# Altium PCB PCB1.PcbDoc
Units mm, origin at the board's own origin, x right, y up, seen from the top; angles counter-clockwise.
Board outline 35 x 25 mm, 2 copper layers (Top Layer, Bottom Layer); 9 components, 6 nets, 20 pads, 0 vias.
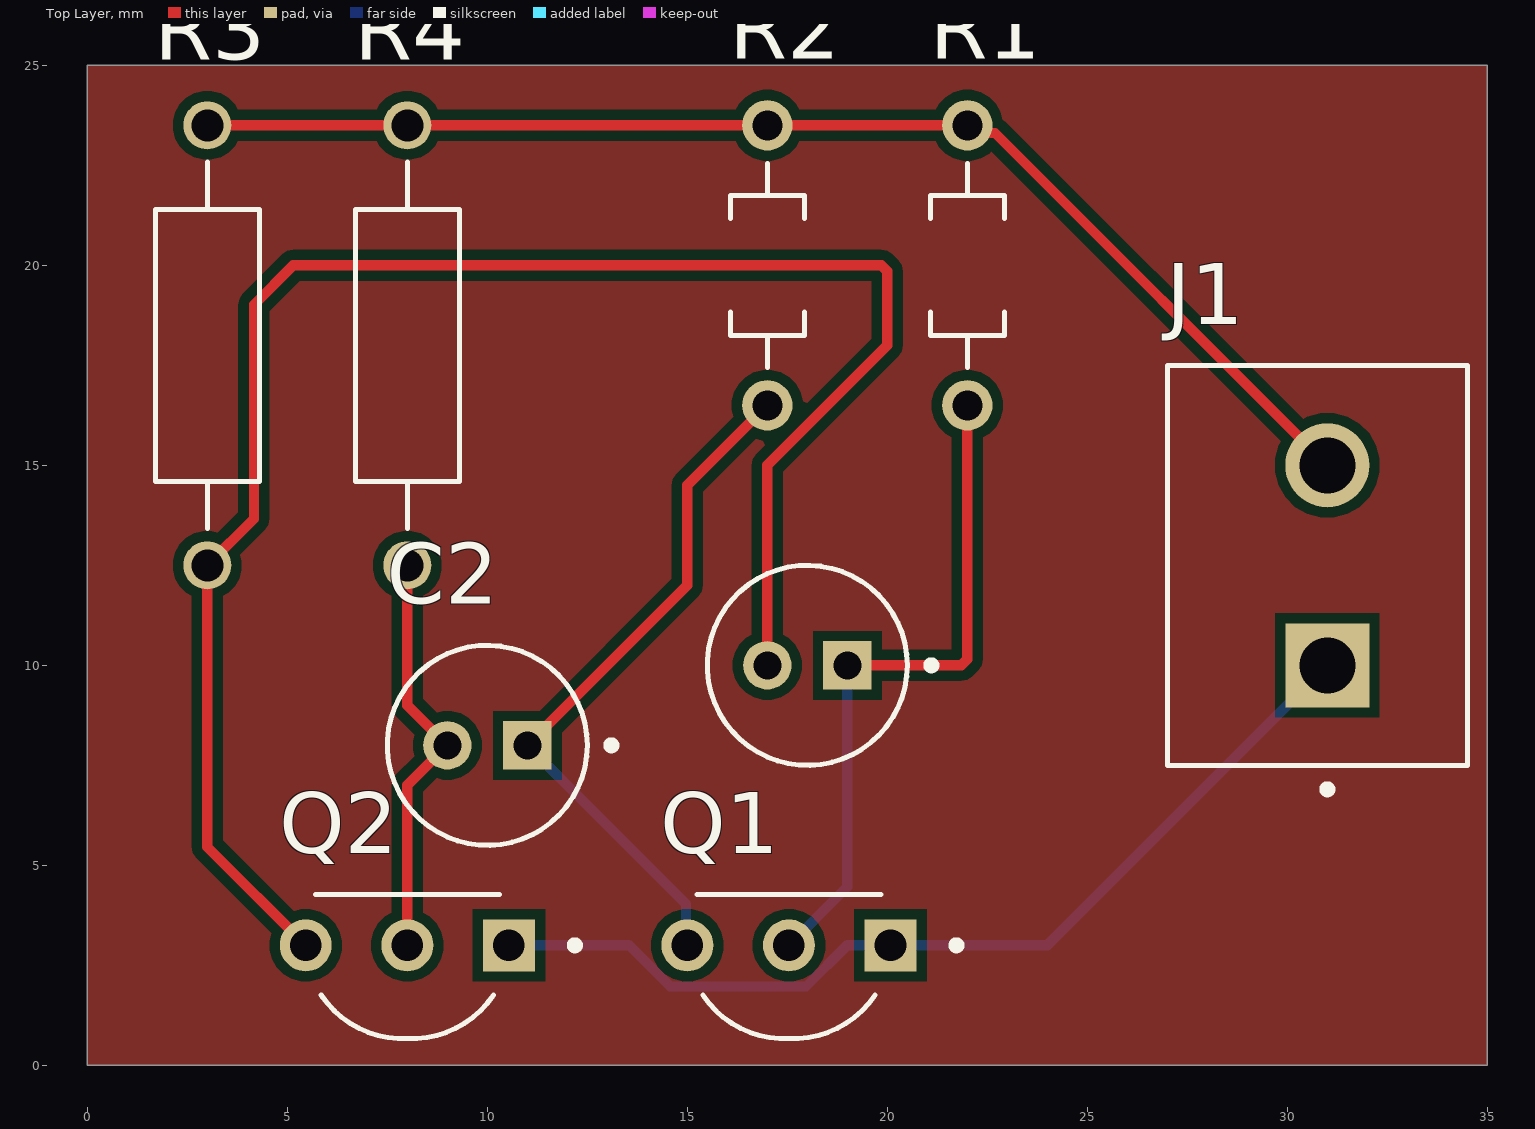
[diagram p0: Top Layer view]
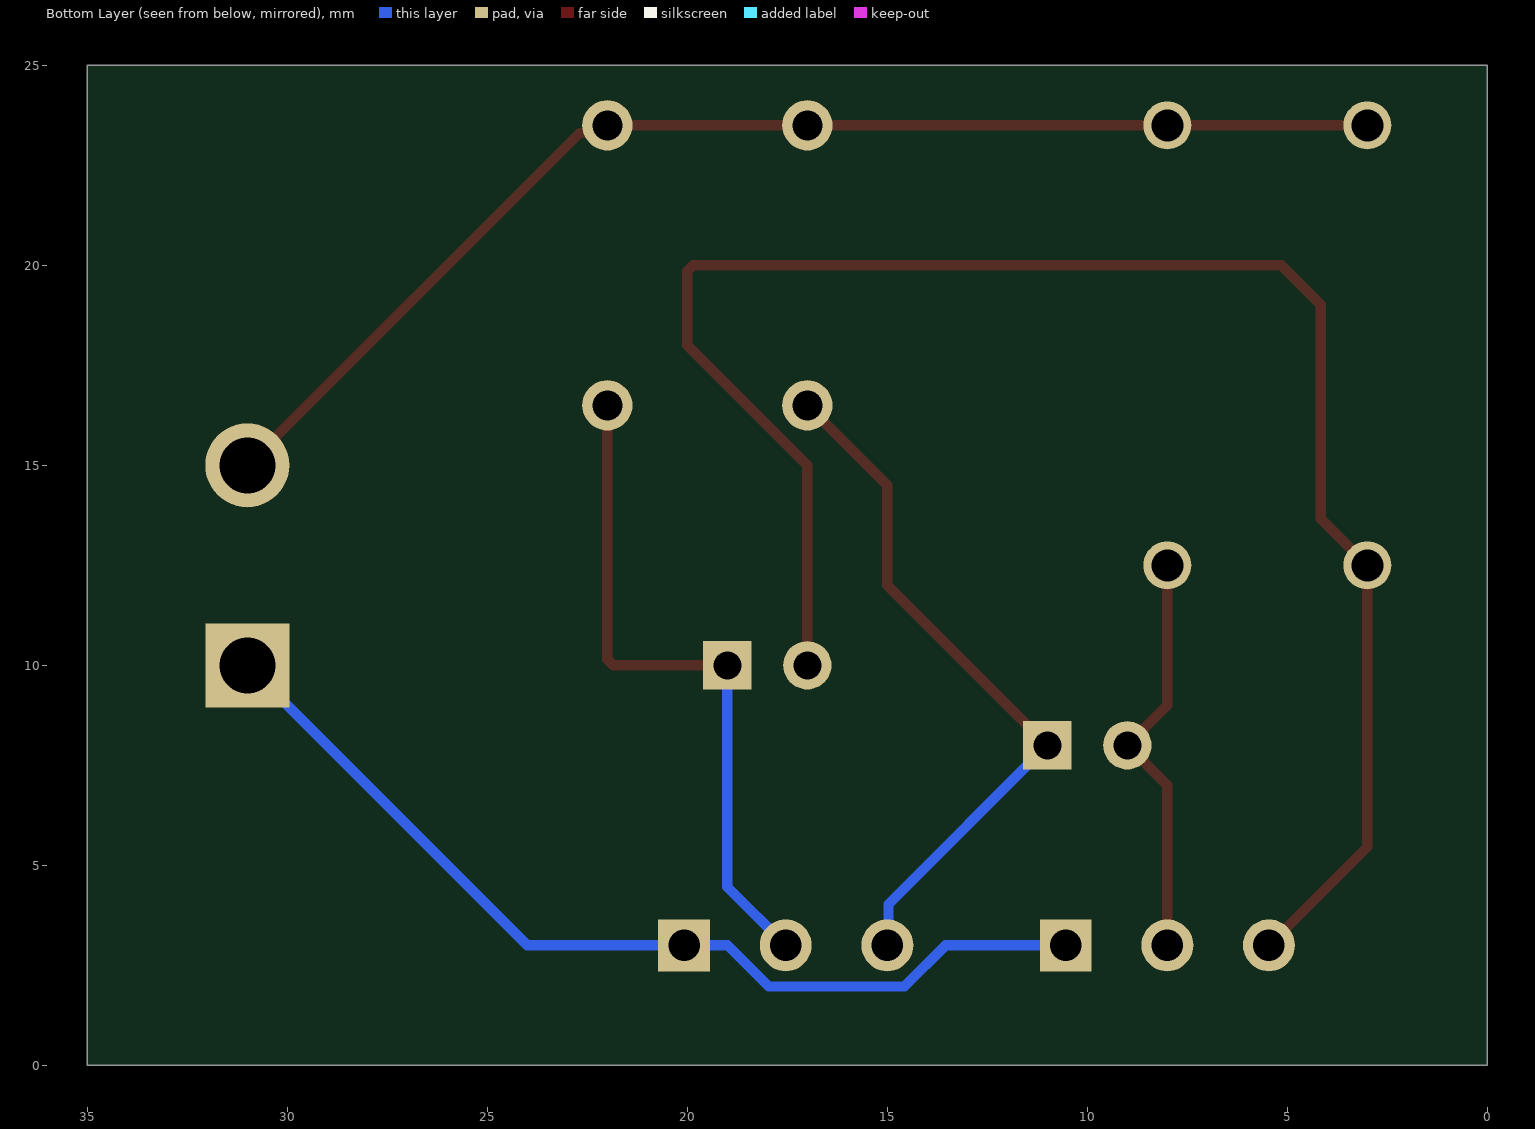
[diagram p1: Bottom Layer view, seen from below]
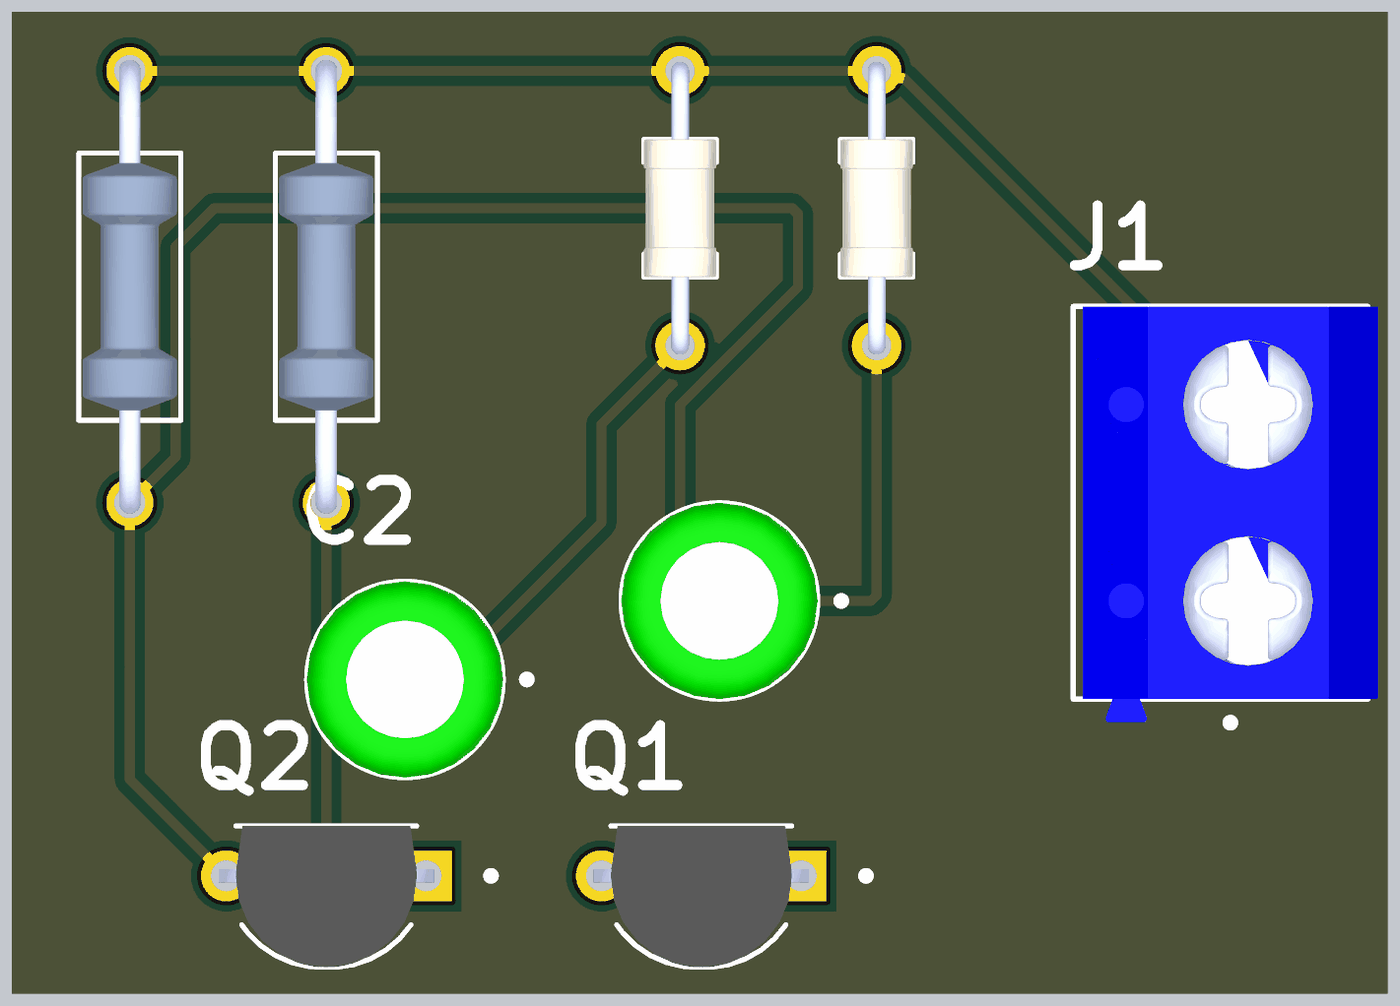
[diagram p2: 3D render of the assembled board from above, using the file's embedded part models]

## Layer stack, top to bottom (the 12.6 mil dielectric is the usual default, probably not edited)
Top Solder: solder mask 0.0102, Solder Resist, Dk 3.5
Top Layer: signal copper 0.0356
Dielectric 1: dielectric 0.32, FR-4, Dk 4.8
Bottom Layer: signal copper 0.0356
Bottom Solder: solder mask 0.0102, Solder Resist, Dk 3.5

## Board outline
0,0 0,25 35,25 35,0

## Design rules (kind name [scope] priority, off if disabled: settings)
Clearance [All] p1: gap=0.254 ignorepadtopadclearanceinfootprint=FALSE except(0: Arc-Hole Track-Hole SMDPad-Hole THPad-Hole Via-Hole Fill-Hole Poly-Hole Region-Hole Text-Hole; 0.3: Arc-Arc Arc-Track Track-Track)
PolygonConnect [All] p1: connectstyle=Relief reliefconductorwidth=0.254 reliefentries=4 polygonreliefangle="90 Angle" airgapwidth=0.254
RoutingVias [All] p1: holewidth=0.711 width=1.27 viastyle="Through Hole" minholewidth=0.711 minwidth=1.27 maxholewidth=0.711 maxwidth=1.27
SolderMaskExpansion [All] p1: expansion=0.102 istentingtop=FALSE
Width [All] p1: maxlimit=0.254 minlimit=0.254 preferedwidth=0.254
30 further rules are at their usual default settings.

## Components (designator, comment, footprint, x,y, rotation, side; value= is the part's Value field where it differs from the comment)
C1 "UVR1H010MDD" CAPPRD200W50D550H1250 18,10 r180 top
C2 "UVR1H010MDD" CAPPRD200W50D550H1250 10,8 r180 top
J1 "KF301-2P" HANDSON_KF301-2P 31,12.5 r90 top
Q1 "2N3904" TO92254P460H750-3 17.54,3 r180 top
Q2 "2N3904" TO92254P460H750-3 8,3 r180 top
R1 "" RESAD700W45L350D185 22,20 r90 top
R2 "3-1623927-1" RESAD700W45L350D185 17,20 r90 top
R3 "MFR-25FBF52-10K" RESAD1100W55L680D260 3,18 r90 top
R4 "MFR-25FBF52-10K" RESAD1100W55L680D260 8,18 r90 top

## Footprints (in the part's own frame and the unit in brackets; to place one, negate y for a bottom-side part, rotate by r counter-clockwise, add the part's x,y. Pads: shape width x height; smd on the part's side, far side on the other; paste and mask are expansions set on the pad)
CAPPRD200W50D550H1250 [mm]
  rect 1.208x1.208 / inner round 1.208 / far side rect 1.208x1.208 hole 0.7: 1(-1,0)
  round 1.208 hole 0.7: 2(1,0)
  silkscreen extent -3.2,-2.5 2.5,2.5, body extent -2.5,-2.5 2.5,2.5, height 12
HANDSON_KF301-2P [mm]
  rect 2.1x2.1 / inner round 2.1 / far side rect 2.1x2.1 hole 1.4: 1(-2.5,0)
  round 2.1 hole 1.4: 2(2.5,0)
  silkscreen extent -5.7,-3.5 5,4, body extent -5.6,-3.75 5,3.75, height 10
RESAD700W45L350D185 [mm]
  round 1.258 hole 0.75: 1(-3.5,0) 2(3.5,0)
  silkscreen extent -2.55,-0.92 2.55,0.92, body extent -3.72,-0.92 3.72,0.92, height 1.84
RESAD1100W55L680D260 [mm]
  round 1.2 hole 0.8: 1(-5.5,0) 2(5.5,0)
  silkscreen extent -4.58,-1.3 4.58,1.3, body extent -5.77,-1.2 5.77,1.2, height 2.4
TO92254P460H750-3 [mm]
  rect 1.298x1.298 / inner round 1.298 / far side rect 1.298x1.298 hole 0.79: 1(-2.54,0)
  round 1.298 hole 0.79: 2(0,0) 3(2.54,0)
  silkscreen extent -4.29,-1.27 2.3,2.33, body extent -2.74,-1.27 2.74,2.33, height 8.09

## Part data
C1 C2: "1 ÂµF 50 V Aluminum Electrolytic Capacitors Radial, Can - 2000 Hrs @ 85Â°C", Package="Radial Nichicon"
J1: "2 Pin Terminal Block 5mm Pitch", Package=None
Q1 Q2: "BJT, TO-92, 40V, 200mA, NPN, 0.625W, 150Â°C", Package="TO-92 Diotec"
R1: library part 3-1623927-1, "1 MOhms Â±5% 0.25W, 1/4W Through Hole Resistor Axial - Carbon Film", Package=None
R2: "1 MOhms Â±5% 0.25W, 1/4W Through Hole Resistor Axial - Carbon Film", Package=None
R3 R4: "10.2 kOhms Â±1% 0.25W, 1/4W Through Hole Resistor Axial - Metal Film", Package="RADIAL-2 YAGEO"

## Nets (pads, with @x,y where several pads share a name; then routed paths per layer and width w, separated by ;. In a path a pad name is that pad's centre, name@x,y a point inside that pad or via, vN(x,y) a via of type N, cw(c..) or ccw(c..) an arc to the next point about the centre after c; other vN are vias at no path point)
+12V: J1.2 R1.2 R2.2 R3.2 R4.2 | length 31.5
  Top Layer w0.254: R3.2 R4.2 R2.2 R1.2 22.192,23.308 22.692,23.308 J1.2
GND: J1.1 Q1.1 Q2.1 | length 24.2
  Bottom Layer w0.254: Q2.1 13.543,3 14.573,1.97 17.967,1.97 18.997,3 Q1.1 24,3 J1.1
NetC1_1: C1.1 Q1.2 R1.1 | length 17
  Top Layer w0.254: C1.1 21.851,10 22,10.149 R1.1
  Bottom Layer w0.254: Q1.2 19,4.46 C1.1
NetC1_2: C1.2 Q2.3 R3.1 | length 44.9
  Top Layer w0.254: Q2.3 3,5.46 R3.1 4.165,13.665 4.165,19.016 5.149,20 19.851,20 20,19.851 20,18 17,15 C1.2
NetC2_1: C2.1 Q1.3 R2.1 | length 17.6
  Top Layer w0.254: C2.1 15,12 15,14.5 R2.1
  Bottom Layer w0.254: C2.1 14.97,4.03 14.97,3.03 Q1.3
NetC2_2: C2.2 Q2.2 R4.1 | length 10.3
  Top Layer w0.254: Q2.2 8,7 C2.2 8,9 R4.1

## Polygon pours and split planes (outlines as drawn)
no net on Top Layer "NONET_L01_P000" (solid, pour order 0): 0,25 35,25 35,0 0,0

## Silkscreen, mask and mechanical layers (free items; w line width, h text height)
Mechanical 1:
  the board outline again, w0.254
